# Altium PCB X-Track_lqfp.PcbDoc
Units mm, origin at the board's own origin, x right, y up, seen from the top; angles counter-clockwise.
Board outline 32.26 x 36.83 mm, 2 copper layers (Top Layer, Bottom Layer); 71 components, 50 nets, 272 pads, 61 vias.
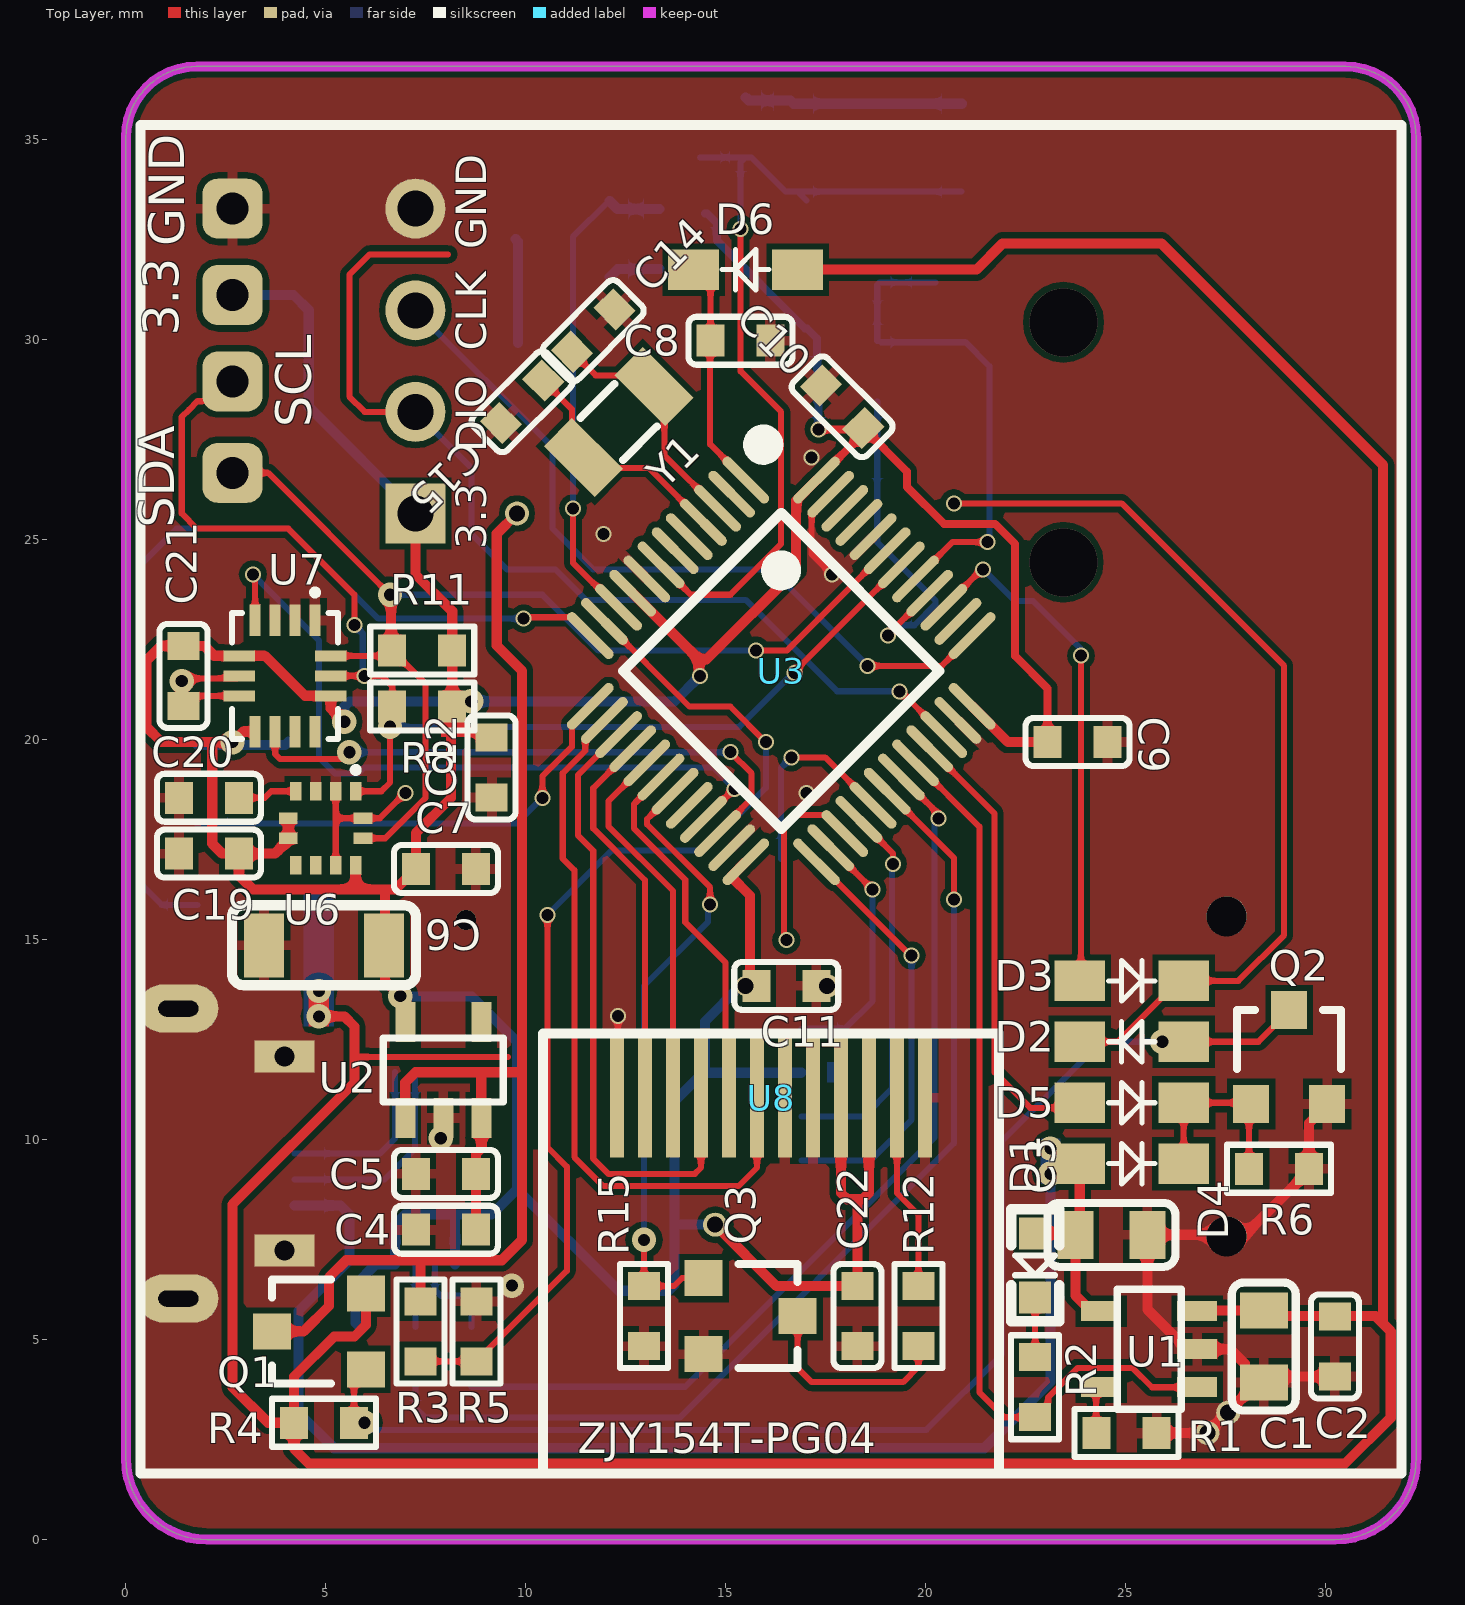
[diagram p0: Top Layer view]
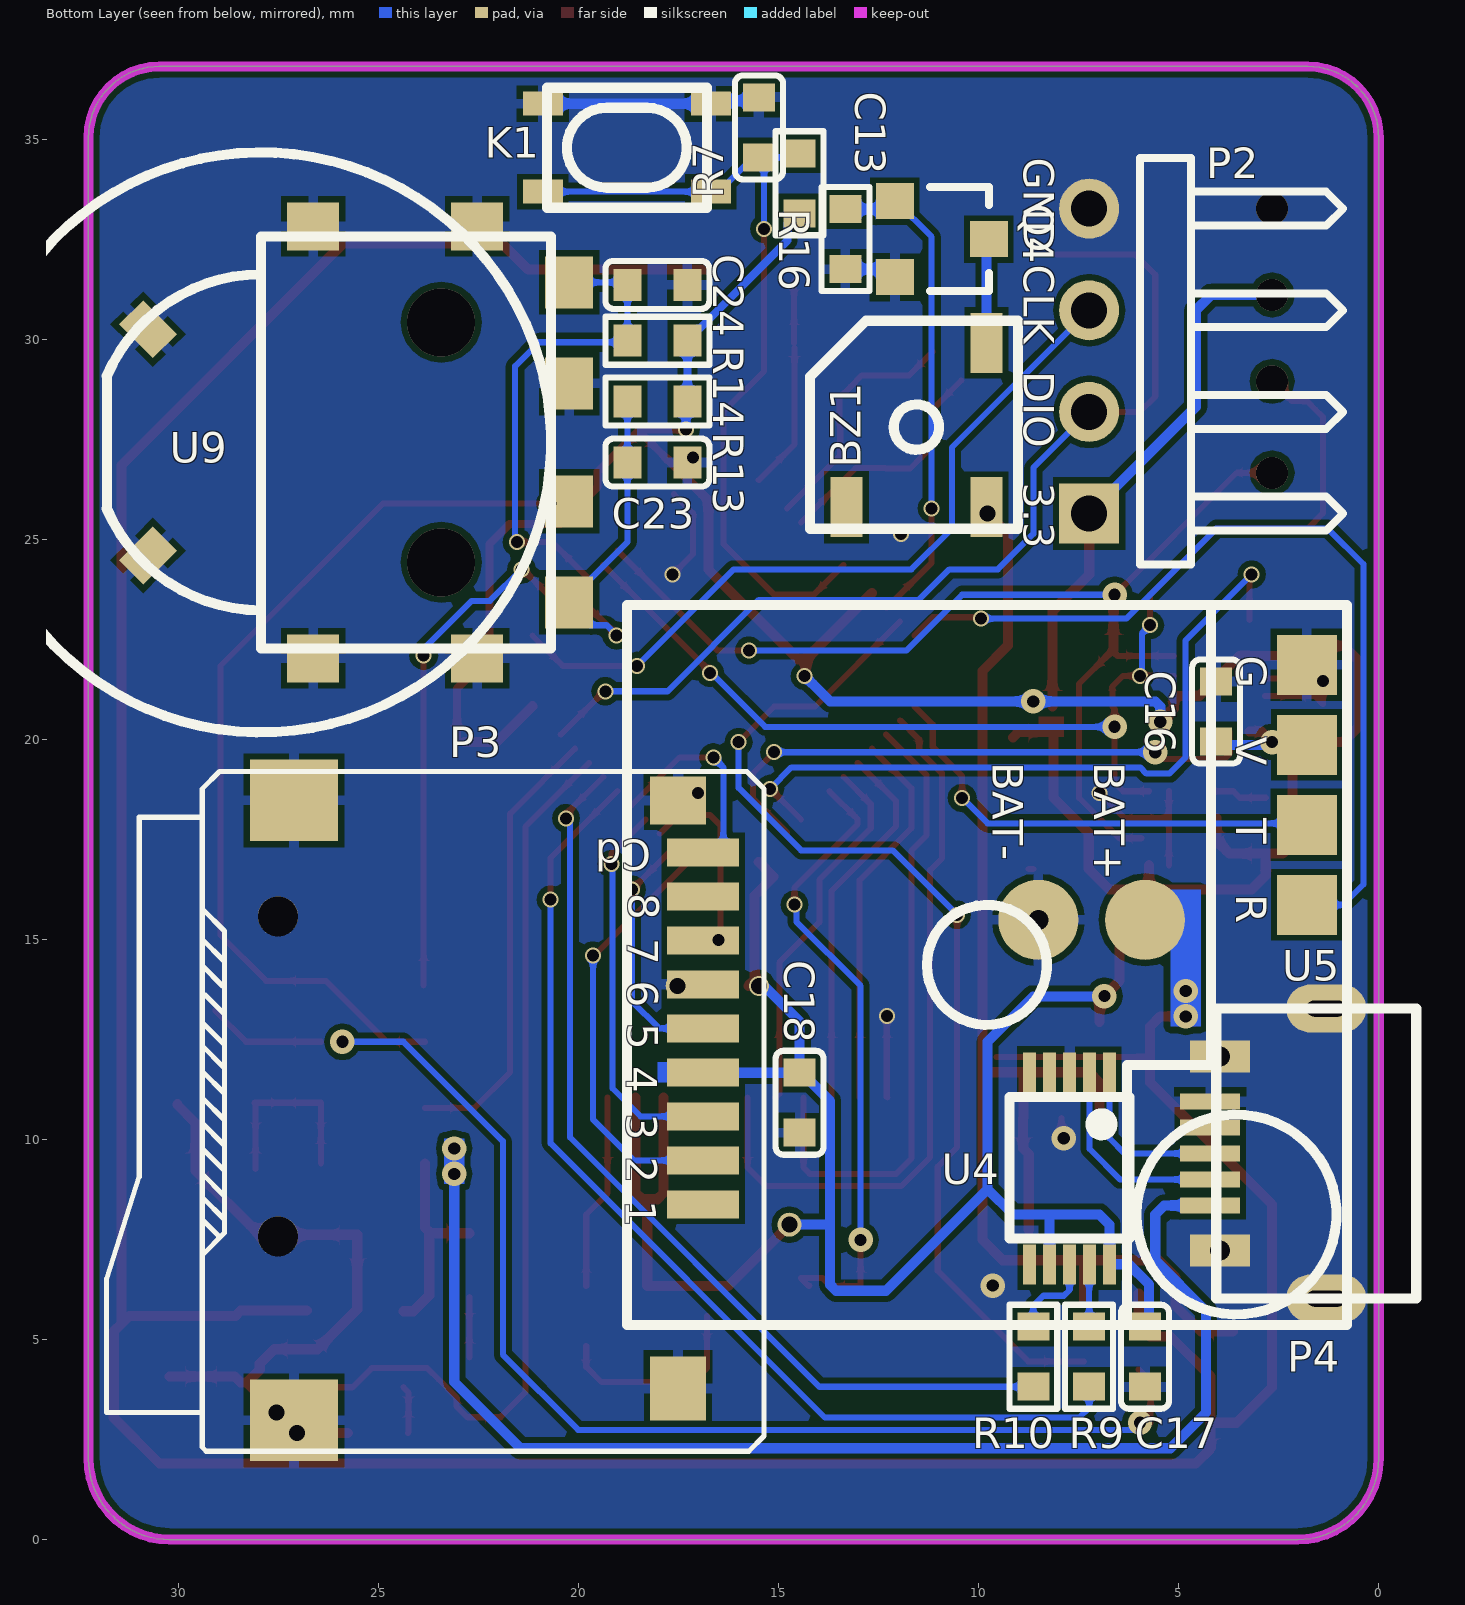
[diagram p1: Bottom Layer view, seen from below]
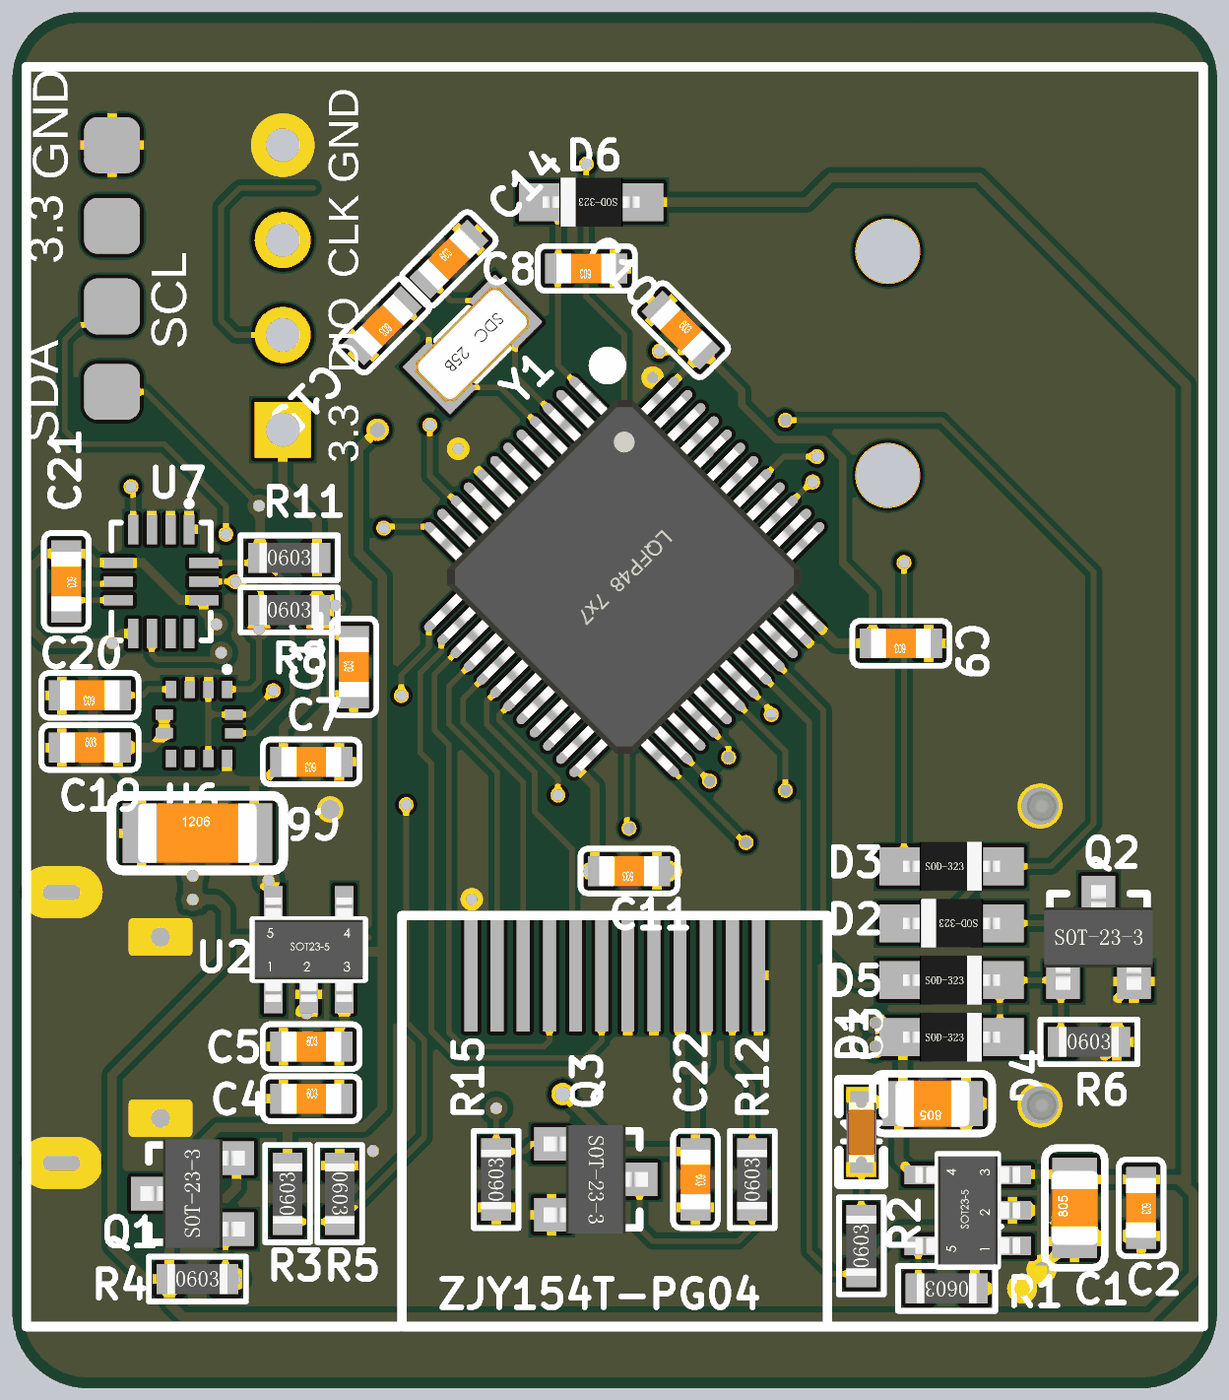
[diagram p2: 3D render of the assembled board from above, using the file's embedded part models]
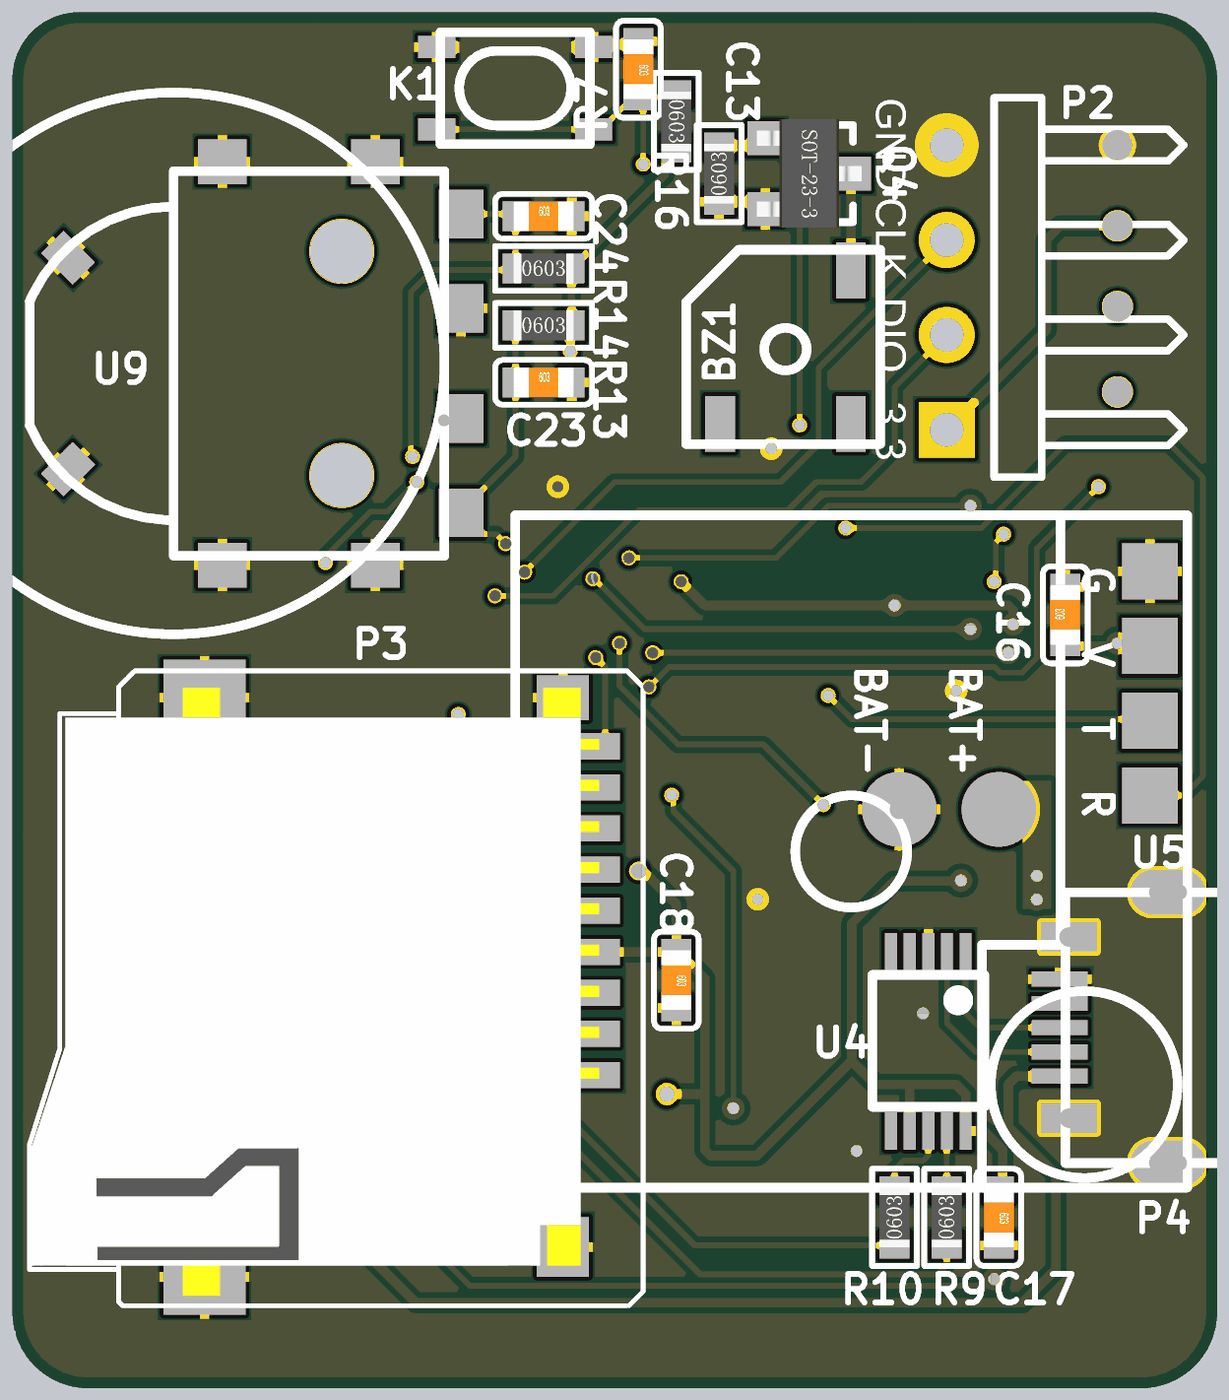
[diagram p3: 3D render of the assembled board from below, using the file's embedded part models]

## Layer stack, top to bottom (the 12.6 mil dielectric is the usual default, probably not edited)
Top Solder: solder mask 0.0102, Solder Resist, Dk 3.5
Top Layer: signal copper 0.0356
Dielectric 1: dielectric 0.32, FR-4, Dk 4.8
Bottom Layer: signal copper 0.0356
Bottom Solder: solder mask 0.0102, Solder Resist, Dk 3.5

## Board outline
0,2.032 0,35.052 cw(c1.778,35.052) 1.778,36.83 30.48,36.83 cw(c30.48,35.052) 32.258,35.052 32.258,2.032 cw(c30.226,2.032) 30.226,0 2.032,0 cw(c2.032,2.032)

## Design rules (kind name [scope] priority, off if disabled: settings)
Clearance [All] p1: gap=0.152 ignorepadtopadclearanceinfootprint=FALSE except(0: Arc-Hole Track-Hole SMDPad-Hole THPad-Hole Via-Hole Fill-Hole Poly-Hole Region-Hole Text-Hole)
ComponentClearance [All] p1 off: gap=0.254 collisioncheckmode=3 verticalgap=0.254 showdistances=FALSE
HoleSize [All] p1 off: absolutevalues=TRUE maxlimit=2.54 minlimit=0.025 maxpercent=80.000 minpercent=20.000
HoleToHoleClearance [All] p1 off: gap=0.254 allowstackedmicrovias=TRUE
LayerPairs [All] p1 off: enforce=TRUE
MinimumSolderMaskSliver [All] p1 off: minsoldermaskwidth=0.254
NetAntennae [All] p1 off: netantennaetolerance=0
PlaneConnect [All] p1: pad.planeconnectstyle=Relief pad.reliefexpansion=0.508 pad.reliefentries=4 pad.reliefconductorwidth=0.254 pad.reliefairgap=0.152 via.planeconnectstyle=Direct via.reliefexpansion=0.508 via.reliefentries=4 via.reliefconductorwidth=0.254 via.reliefairgap=0.152
PolygonConnect [All] p1: thpad.connectstyle=Direct thpad.reliefconductorwidth=0.254 thpad.reliefentries=4 thpad.polygonreliefangle="90 Angle" thpad.airgapwidth=0.152 smdpad.connectstyle=Relief smdpad.reliefconductorwidth=0.254 smdpad.reliefentries=4 smdpad.polygonreliefangle="90 Angle" smdpad.airgapwidth=0.152 via.connectstyle=Direct via.reliefconductorwidth=0.254 via.reliefentries=4 via.polygonreliefangle="90 Angle" via.airgapwidth=0.152
RoutingVias [All] p1: holewidth=0.305 width=0.61 viastyle="Through Hole" minholewidth=0.305 minwidth=0.61 maxholewidth=0.305 maxwidth=0.61
SilkToSilkClearance [All] p1 off: silktosilkclearance=0.254
SilkToSolderMaskClearance [IsPad] p1 off: minsilkscreentomaskgap=0.254 clearancetoexposedcopper=TRUE
SolderMaskExpansion [All] p1: expansion=0.102 istentingtop=FALSE
Width [All] p1: maxlimit=2.54 minlimit=0.152 preferedwidth=0.152
21 further rules are at their usual default settings.

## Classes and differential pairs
component class X-Track_Power: BAT+ BAT- C1 C2 C3 C4 C5 C6 C7 D1 D2 D3 D4 D5 Q1 Q2 R1 R2 R3 R4 R5 R6 U1 U2
component class X-Track_Sheet: 3.3 BZ1 C8 C9 C10 C11 C12 C13 C14 C15 C16 C17 C18 C19 C20 C21 C22 C23 C24 D6 GND K1 P2 P3 P4 Q3 Q4 R7 R8 R9 R10 R11 R12 R13 R14 R15 R16 SCL SDA U3 U4 U5 U6 U7 U8 U9 Y1

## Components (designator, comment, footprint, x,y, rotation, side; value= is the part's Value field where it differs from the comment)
3.3 "PAD1" PAD1-SMD-C 2.667,31.115 r0 top
BAT+ "BAT_IN" Pad_B 5.842,15.494 r90 bottom
BAT- "GND" Pad_B 8.509,15.494 r90 bottom
BZ1 "Buzzer" 蜂鸣器_SMD5020 11.557,27.813 r90 bottom
C1 "4.7UF" 电容_C0805 28.448,4.826 r90 top
C2 "104" 电容_C0603 30.226,4.826 r270 top
C3 "4.7UF" 电容_C0805 24.638,7.62 r180 top
C4 "104" 电容_C0603 8.001,7.747 r0 top
C5 "106" 电容_C0603 8.001,9.144 r0 top
C6 "22uF" 电容_C1206 4.953,14.859 r0 top
C7 "104" 电容_C0603 8.001,16.764 r180 top
C8 "104" 电容_C0603 15.367,29.972 r180 top
C9 "105" 电容_C0603 23.793,19.939 r180 top
C10 "105" 电容_C0603 17.907,28.321 r315 top
C11 "105" 电容_C0603 16.51,13.843 r180 top
C12 "105" 电容_C0603 9.144,19.304 r90 top
C13 "104" 电容_C0603 15.494,35.306 r270 bottom
C14 "22pf" 电容_C0603 11.684,30.226 r45 top
C15 "22pf" 电容_C0603 9.906,28.448 r225 top
C16 "105" 电容_C0603 4.064,20.701 r90 bottom
C17 "105" 电容_C0603 5.842,4.572 r270 bottom
C18 "104" 电容_C0603 14.478,10.922 r270 bottom
C19 "104" 电容_C0603 2.076,17.149 r0 top
C20 "104" 电容_C0603 2.076,18.546 r180 top
C21 "104" 电容_C0603 1.441,21.594 r270 top
C22 "104" 电容_C0603 18.288,5.588 r270 top
C23 "104" 电容_C0603 18.034,26.924 r180 bottom
C24 "104" 电容_C0603 18.034,31.369 r180 bottom
D1 "red" LED_0603 22.733,6.858 r270 top
D2 "1N4148" 二极管_SOD-323 25.146,12.446 r180 top
D3 "1N4148" 二极管_SOD-323 25.146,13.97 r0 top
D4 "1N4148" 二极管_SOD-323 25.146,9.398 r0 top
D5 "1N4148" 二极管_SOD-323 25.146,10.922 r0 top
D6 "1N4007" 二极管_SOD-323 15.494,31.75 r180 top
GND "PAD1" PAD1-SMD-C 2.667,33.274 r0 top
K1 "SKRP" 开关按键_SKRP 18.796,34.798 r0 bottom
P2 "Header 4" HDR1X4H 7.239,25.654 r90 bottom
P3 "Micro_SD" 接插件_Micro_SD 16.891,8.382 r270 bottom locked
P4 "MICRO USB" "接插件_MICRO 牛角插座 USB 直边" 4.064,9.652 r270 bottom
Q1 "AO3401" MOS_SOT-23 4.826,5.207 r90 top
Q2 "AON3400" MOS_SOT-23 29.083,12.065 r0 top
Q3 "AO3400" MOS_SOT-23 15.621,5.588 r270 top
Q4 "AO3400" MOS_SOT-23 10.922,32.512 r270 bottom
R1 "2K" 电阻_R0603 25.019,2.667 r180 top
R2 "1K" 电阻_R0603 22.733,3.81 r90 top
R3 "20K" 电阻_R0603 7.366,5.207 r90 top
R4 "20K" 电阻_R0603 4.953,2.921 r0 top
R5 "20K" 电阻_R0603 8.763,5.207 r270 top
R6 "20K" 电阻_R0603 28.829,9.271 r0 top
R7 "10K" 电阻_R0603 14.478,33.909 r270 bottom
R8 "10K" 电阻_R0603 7.41,20.832 r0 top
R9 "100R" 电阻_R0603 7.239,4.572 r90 bottom
R10 "100R" 电阻_R0603 8.636,4.572 r90 bottom
R11 "10K" 电阻_R0603 7.41,22.229 r0 top
R12 "10R" 电阻_R0603 19.812,5.588 r90 top
R13 "10K" 电阻_R0603 18.034,28.448 r180 bottom
R14 "10K" 电阻_R0603 18.034,29.972 r180 bottom
R15 "10K" 电阻_R0603 12.954,5.588 r90 top
R16 "10K" 电阻_R0603 13.335,32.512 r90 bottom
SCL "PAD1" PAD1-SMD-C 2.667,28.956 r0 top
SDA "PAD1" PAD1-SMD-C 2.667,26.67 r0 top
U1 "MCP73831" SOT23-5 26.784,3.81 r90 top
U2 "LP5907-3.3" SOT23-5 6.985,10.541 r0 top
U3 "AT32F403ACGU7" "LQFP48 7X7_L" 16.383,21.717 r225 top
U4 "CH340E" 串口_MSOP10 6.731,11.684 r0 bottom
U5 "HT1818Z3G5L" GPS-HTZN 18.796,23.368 r270 bottom
U6 "LIS3MDL" LGA-12_L2.0-W2.0-P0.50-BL 4.997,17.784 r180 top
U7 "LSM6DSM" LGA-14_L3.0-W2.5-P0.50-BL 3.981,21.594 r180 top
U8 "IPS154-12" "ZJY154T-PG04 FPC 0.7MM" 16.129,11.049 r270 top locked
U9 "Rotary Encoder" SIQ-02FVS3 27.94,27.432 r90 bottom locked
Y1 "32.768K" 晶振_3215 12.319,27.94 r225 top

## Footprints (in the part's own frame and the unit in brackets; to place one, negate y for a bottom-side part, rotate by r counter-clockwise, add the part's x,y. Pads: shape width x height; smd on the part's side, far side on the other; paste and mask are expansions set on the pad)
GPS-HTZN [mm]
  rect 1.5x1.5 smd: 1(1.5,17) 2(3.5,17) 3(5.5,17) 4(7.5,17)
  silkscreen extent 0,0 18,18
HDR1X4H [mm] "Connector; Header; 4 Position; Right Angle"
  rect 1.5x1.5 hole 0.9: 1(0,0)
  round 1.5 hole 0.9: 2(2.54,0) 3(5.08,0) 4(7.62,0)
  silkscreen extent -1.27,-6.35 8.89,-1.27
LED_0603 [mm]
  rect 0.8x0.8 smd paste-0.1: A(-0.8,0) K(0.8,0)
  silkscreen extent -1.4,-0.6 1.4,0.6, body extent -0.8,-0.4 0.82,0.4, height 0.6
LGA-12_L2.0-W2.0-P0.50-BL [mm]
  rect 0.28x0.465 smd: 1(-0.75,-0.925) 2(-0.25,-0.925) 3(0.25,-0.925) 4(0.75,-0.925) 7(0.75,0.925) 8(0.25,0.925) 9(-0.25,0.925) 10(-0.75,0.925)
  rect 0.465x0.28 smd: 5(0.933,-0.25) 6(0.933,0.25) 11(-0.933,0.25) 12(-0.933,-0.25)
  silkscreen extent -0.82,-1.53 -0.68,-1.38
LGA-14_L3.0-W2.5-P0.50-BL [mm]
  rect 0.28x0.785 smd: 1(-0.75,-1.393) 2(-0.25,-1.393) 3(0.25,-1.393) 4(0.75,-1.393) 8(0.75,1.393) 9(0.25,1.393) 10(-0.25,1.393) 11(-0.75,1.393)
  rect 0.785x0.28 smd: 5(1.142,-0.5) 6(1.142,0) 7(1.142,0.5) 12(-1.142,0.5) 13(-1.142,0) 14(-1.142,-0.5)
  silkscreen extent -1.33,-2.16 1.33,1.58
"LQFP48 7X7_L" [mm] "48脚，体宽7x7mm，脚距0.5mm"
  oval 0.25x1.55 smd: 1(-2.75,-4) 2(-2.25,-4) 3(-1.75,-4) 4(-1.25,-4) 5(-0.75,-4) 6(-0.25,-4) 7(0.25,-4) 8(0.75,-4) 9(1.25,-4) 10(1.75,-4) 11(2.25,-4) 12(2.75,-4) 25(2.75,4) 26(2.25,4) 27(1.75,4) 28(1.25,4) 29(0.75,4) 30(0.25,4) 31(-0.25,4) 32(-0.75,4) 33(-1.25,4) 34(-1.75,4) 35(-2.25,4) 36(-2.75,4)
  oval 1.55x0.25 smd: 13(4,-2.75) 14(4,-2.25) 15(4,-1.75) 16(4,-1.25) 17(4,-0.75) 18(4,-0.25) 19(4,0.25) 20(4,0.75) 21(4,1.25) 22(4,1.75) 23(4,2.25) 24(4,2.75) 37(-4,2.75) 38(-4,2.25) 39(-4,1.75) 40(-4,1.25) 41(-4,0.75) 42(-4,0.25) 43(-4,-0.25) 44(-4,-0.75) 45(-4,-1.25) 46(-4,-1.75) 47(-4,-2.25) 48(-4,-2.75)
  silkscreen extent -3.93,-4.57 2.79,2.79, body extent -4.5,-4.5 4.5,4.5, height 1.45
MOS_SOT-23 [mm]
  rect 0.9x0.95 smd: 1(-0.95,-1.175) 2(0,1.175) 3(0.95,-1.175)
  silkscreen extent -1.3,-0.3 1.3,1.18, body extent -1.45,-1.4 1.45,1.4, height 1.2
PAD1-SMD-C [mm] "引线焊盘"
  rrect50% 1.5x1.5 smd: 1(0,0)
Pad_B [mm]
  round 2 smd: 1(0,0)
SIQ-02FVS3 [mm]
  rect 1.3x1.2 smd: 1(-4,-7.7) 2(-1.475,-7.7) 3(1.475,-7.7) 4(4,-7.7)
  rect 1.2x1.3 smd: 5(-5.4,-5.4) 5(-5.4,-1.3) 5(5.4,-5.4) 5(5.4,-1.3)
  rect 0.85x1.2 smd rot 45: 5(-2.828,2.828)
  rect 0.85x1.2 smd rot 135: 5(2.828,2.828)
  silkscreen extent -7.25,-7.25 7.25,7.25
SOT23-5 [mm]
  rect 0.5x1 smd: 1(0,0) 2(0.95,0) 3(1.9,0) 4(1.9,2.4) 5(0,2.4)
  silkscreen extent -0.55,0.4 2.45,2, body extent -0.5,-0.2 2.4,2.6, height 1.09
"ZJY154T-PG04 FPC 0.7MM" [mm]
  rect 3x0.35 smd: 1(0,3.85) 2(0,3.15) 3(0,2.45) 4(0,1.75) 5(0,1.05) 6(0,0.35) 7(0,-0.35) 8(0,-1.05) 9(0,-1.75) 10(0,-2.45) 11(0,-3.15) 12(0,-3.85)
  silkscreen extent -24.32,-15.76 9.4,15.76
串口_MSOP10 [mm]
  rect 0.32x1 smd: 1(0,0) 2(0.5,0) 3(1,0) 4(1.5,0) 5(2,0) 6(2,4.8) 7(1.5,4.8) 8(1,4.8) 9(0.5,4.8) 10(0,4.8)
  silkscreen extent -0.5,0.62 2.5,4.15
二极管_SOD-323 [mm]
  rect 1.27x1.016 smd: A(-1.3,0) K(1.3,0)
  silkscreen extent -0.58,-0.51 0.58,0.51, body extent -1.3,-0.65 1.3,0.65, height 1
开关按键_SKRP [mm]
  rect 1x0.6 smd: 1(-2.1,-1.1) 1(2.1,-1.1) 2(-2.1,1.1) 2(2.1,1.1)
  silkscreen extent -2,-1.5 2,1.5
"接插件_MICRO 牛角插座 USB 直边" [mm]
  oval 1.2x2 hole 0.4 slot 1 at 90 deg: 0(-3.625,2.75) 0(3.625,2.75)
  rect 0.8x1.5 hole 0.5: 0(-2.425,0.1) 0(2.425,0.1)
  rect 0.4x1.5 smd: 1(1.3,-0.15) 2(0.65,-0.15) 3(0,-0.15) 4(-0.65,-0.15) 5(-1.3,-0.15)
  silkscreen extent -3.62,0 3.62,5
接插件_Micro_SD [mm]
  rect 2.032x2.2 smd: 0(-10.1,-10.227) 0(5.4,-10.227)
  rect 1.2x1.4 smd: 0(-10.1,-0.627)
  round 1 hole 1 unplated: 0(-7.2,-10.627) 0(0.8,-10.627)
  rect 1.6x1.4 smd: 0(4.6,-0.627)
  rect 0.7x1.8 smd: 1(0,0) 2(-1.1,0) 3(-2.2,0) 4(-3.3,0) 5(-4.4,0) 6(-5.5,0) 7(-6.6,0) 8(-7.7,0) 9(-8.8,0)
  silkscreen extent -10.82,-14.91 6.17,1.52, body extent -10.37,-14.85 5.9,0.34, height 1.8
晶振_3215 [mm] "XTAL SMD 3.2 x 1.5 mm"
  rect 1x1.8 smd: 1(-1.25,0) 2(1.25,0)
  silkscreen extent -0.6,-0.75 0.6,0.75, body extent -1.6,-0.75 1.6,0.75, height 0.81
电容_C0603 [mm]
  rect 0.7x0.8 smd: 1(-0.75,0) 2(0.75,0)
  silkscreen extent -1.3,-0.6 1.3,0.6, body extent -0.8,-0.4 0.8,0.4, height 0.3
电容_C0805 [mm]
  rect 0.9x1.2 smd: 1(-0.9,0) 2(0.9,0)
  silkscreen extent -1.6,-0.8 1.6,0.8, body extent -1,-0.62 1,0.63, height 0.77
电容_C1206 [mm]
  rect 1x1.6 smd: 1(-1.5,0) 2(1.5,0)
  silkscreen extent -2.3,-1 2.3,1, body extent -1.6,-0.8 1.6,0.8, height 1
电阻_R0603 [mm]
  rect 0.7x0.8 smd: 1(-0.75,0) 2(0.75,0)
  silkscreen extent -1.3,-0.6 1.3,0.6, body extent -0.8,-0.4 0.8,0.4, height 0.45
蜂鸣器_SMD5020 [mm]
  rect 1.5x0.8 smd: 0(-2,1.75) 1(-2,-1.75) 2(2.108,-1.753)
  silkscreen extent -2.54,-2.54 2.66,2.66

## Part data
3.3 GND SCL SDA: "引线焊盘"
BAT+ BAT-: library part Pad
BZ1: library part BZ
C1 C2 C3 C4 C5 C6 C7 C8 C9 C10 C11 C12 C13 C14 C15 C16 C17 C18 C19 C20 C21 C22 C23 C24: library part cap
D1: library part LED
D2 D3 D4 D5 D6: library part Diode, _Current=1A, _Voltage=40V
K1: library part SW-PB
P2: "Header, 4-Pin"
P3: _Value=TF,9PIN
P4: library part "MICRO USB 5PIN", _Value=5PIN
Q1: library part MOSFET-P, _Current=40A, _Voltage=20V
Q2 Q3 Q4: library part MOSFET-N, _Current=150A, _Voltage=30V
R1 R2 R3 R4 R5 R6 R7 R9 R10 R15 R16: library part Res
R8 R11 R12 R13 R14: library part Res, _Power=1/8W
U1: "线性充电管理控制器"
U2: library part LP5907, "LDO"
U3: library part AT32F403CGU6
U6: library part LIS3DMDL
Y1: library part XTAL_A

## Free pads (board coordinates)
  round 0.6 hole 0.4: 2(9.779,25.654) 3(27.039,2.667) 4(27.559,3.175) 5(14.732,7.874) 6(17.526,13.843)

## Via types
v1: diameter 0.4, hole 0.3, Top Layer to Bottom Layer, 36 vias
v2: diameter 0.61, hole 0.305, Top Layer to Bottom Layer, tented both sides, 17 vias
v3: diameter 0.8, hole 0.8, Top Layer to Bottom Layer, 4 vias
v4: diameter 1.7, hole 1.7, Top Layer to Bottom Layer, 2 vias
v5: diameter 0.5, hole 0.5, Top Layer to Bottom Layer, 1 vias
v6: diameter 0.5, hole 0.4, Top Layer to Bottom Layer, 1 vias

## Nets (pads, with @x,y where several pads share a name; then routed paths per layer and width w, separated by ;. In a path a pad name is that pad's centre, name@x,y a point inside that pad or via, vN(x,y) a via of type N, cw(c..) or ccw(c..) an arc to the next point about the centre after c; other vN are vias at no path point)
3V3: 3.3.1 C6.2 C7.2 C9.2 C10.2 C11.2 C12.2 C16.1 C17.1 C18.1 C19.2 C21.1 C22.1 P2.1 P3.4 pad.5 R7.2 R8.2 R11.2 R13.2 R14.2 U2.5 U3.9 U3.24 U3.36 U3.48 U4.7 U4.10 U5.2 U6.5 U6.6 U6.10 U7.5 U7.8 U7.12 U8.3 U8.4 | length 134.9
  Top Layer w0.2: U3.48 C10.2@18.437,27.66 ; v1(17.32,27.755) 18.402,27.755 C10.2 19.531,26.697 19.531,26.316 20.458,25.389 21.733,25.389 22.233,24.889 22.233,22.09 23.043,21.28 C9.2
  Top Layer w0.254: U7.8 2.929,20.201 v2(2.667,19.939) 2.159,19.939 ; U6.5 4.064,17.486 3.727,17.149 C19.2 ; v2(5.461,20.447) 5.123,20.785 U7.12 4.481,21.094 3.481,22.094 U7.5 2.211,22.094 1.961,22.344 C21.1 0.881,22.344 0.508,21.971 0.508,20.32 0.889,19.939 2.159,19.939 ; U6.10 5.747,16.256 ; U2.5 6.985,13.462 6.477,13.97 6.477,16.256 ; P2.1 7.239,24.13 8.16,23.209 R11.2 R8.2 ; C12.2 9.005,20.193 8.128,20.193 8.128,18.542 7.251,17.665 C7.2 6.743,16.256 6.477,16.256 ; U3.9 14.323,22.009 ; v1(14.351,21.59) 14.323,21.618 14.323,22.009 ; pad.5 16.268,6.338 C22.1 18.288,8.509 ; U3.24 15.131,16.576 15.131,16.573 15.602,16.102 15.602,14.001 C11.2 ; U3.48 16.756,25.979 16.756,24.249 14.516,22.009 14.323,22.009 ; U8.4 17.879,8.664 18.034,8.509 18.415,8.509 18.579,8.673 U8.3 ; U3.36 22.05,19.939 C9.2@22.872,19.939 ; 2.159,19.939 2.159,17.399 2.409,17.149 C19.2 ; C19.2 2.826,16.605 3.175,16.256 5.747,16.256 ; 5.747,16.256 6.477,16.256
  Bottom Layer w0.2: R7.2 14.528,33.159 14.778,32.909 14.778,32.478 16.984,30.272 17.034,30.272 17.284,30.022 R14.2 R13.2 17.32,28.412 v1(17.32,27.755)
  Bottom Layer w0.254: U5.2 C16.1@3.981,19.868 ; v2@2.667,19.868 C16.1@3.981,19.868 ; v3(2.667,31.115) 4.191,31.115 4.572,30.734 4.572,28.321 P2.1 ; C16.1 C16.1@3.981,19.868 ; v2(5.461,20.447) 5.461,20.828 5.588,20.955 v2(8.636,20.955) 13.716,20.955 v1(14.351,21.59) ; C17.1 5.741,5.423 5.741,6.376 6.249,6.884 U4.10 6.731,7.874 6.985,8.128 8.231,8.128 ; v2(6.858,13.589) 6.867,13.58 8.645,13.58 9.779,12.446 9.779,8.763 ; U4.7 8.231,8.128 ; pad.5 13.716,7.874 ; v6@15.621,13.843 15.367,13.843 14.478,12.954 C18.1 ; P3.4 16.881,11.672 C18.1 ; 8.231,8.128 9.144,8.128 9.779,8.763 ; 9.779,8.763 12.319,6.223 13.567,6.223 13.716,6.372 13.716,7.874 ; 13.716,7.874 13.716,10.96 14.428,11.672 C18.1
  other v6: 15.494,13.843
BAT: BZ1.1 C4.2 C5.2 pad.2 Q1.2 R3.2 U2.1 U2.3 | length 35.2
  Top Layer w0.254: Q1.2 4.445,5.207 5.08,5.842 5.08,6.556 5.509,6.985 7.366,6.985 ; U2.1 6.985,11.43 7.239,11.684 9.906,11.684 ; R3.2 7.366,6.985 ; C4.2 C5.2 8.751,9.64 8.89,9.779 8.89,10.536 U2.3 8.885,11.679 ; pad.2 9.271,25.146 9.271,22.352 9.906,21.717 9.906,11.684 ; 7.366,6.985 9.398,6.985 9.906,7.493 9.906,11.684
BAT_CHG_DET: R2.1 U1.1 U3.32 | length 22.9
  Top Layer w0.152: U3.32 21.336,17.825 21.336,3.683 21.959,3.06 R2.1 22.783,3.06 23.057,3.334 23.057,3.556 23.505,4.005 23.789,4.289 25.175,4.289 25.654,3.81 U1.1
BAT_DET: R3.1 R5.2 U3.11 | length 26.9
  Top Layer w0.152: R3.1 R5.2 11.024,6.718 11.024,9.323 10.541,9.806 v1(10.541,15.621) ; U3.11 14.09,20.828 15.113,20.828 v1(16.002,19.939)
  Bottom Layer w0.152: v1(10.541,15.621) 12.152,17.232 14.438,17.232 16.002,18.796 v1(16.002,19.939)
BAT_IN: BAT+.1 C1.2 C2.1 D6.A Q1.3 R4.1 U1.3 | length 95.9
  Top Layer w0.152: 5.715,12.065 9.55,12.065
  Top Layer w0.254: v2(4.826,13.081) 5.461,13.081 5.715,12.827 5.715,12.065 5.715,11.43 2.667,8.382 2.667,3.81 3.556,2.921 R4.1 ; Q1.3 6.001,5.366 5.715,5.08 5.207,5.08 4.203,4.076 R4.1 ; D6.A 21.266,31.75 21.923,32.407 25.886,32.407 31.432,26.86 31.432,5.397 ; U1.3@26.797,5.726 C1.2 28.586,5.588 30.226,5.588 31.242,5.588 31.432,5.397 ; R4.1 4.203,2.274 4.572,1.905 30.48,1.905 31.623,3.048 31.623,5.207 31.432,5.397
  other v2: 4.826,13.716
BUZZ: Q4.1 R16.2 U3.10 | length 12.4
  Top Layer w0.152: v1(11.176,25.781) 11.176,24.423 12.291,23.308 U3.10
  Bottom Layer w0.152: v1(11.176,25.781) 11.176,32.566 12.072,33.462 Q4.1
  Bottom Layer w0.254: Q4.1 12.297,33.262 R16.2
EC_A: C23.1 R13.1 U3.40 U9.1 | length 8.7
  Top Layer w0.152: v1(19.05,22.606) 19.05,22.616 U3.40
  Bottom Layer w0.152: R13.1 C23.1 18.784,24.938 20.24,23.482 U9.1 20.24,23.382 19.716,22.858 19.302,22.858 v1(19.05,22.606)
EC_B: C24.1 R14.1 U3.41 U9.4 | length 12.4
  Top Layer w0.152: U3.41 20.663,24.937 v1(21.545,24.937)
  Bottom Layer w0.152: R14.1 C24.1 18.847,31.432 U9.4 ; R14.1@18.885,29.934 20.993,29.934 21.59,29.337 21.59,24.981 v1(21.545,24.937)
EC_KEY: D2.K D3.K U9.2 | length 22.9
  Top Layer w0.152: v1(20.701,25.908) 24.892,25.908 28.956,21.844 28.956,15.113 27.813,13.97 D3.K 26.319,13.97 24.795,12.446 D2.K
EC_KEY_DET: D3.A U3.39 | length 13.1
  Top Layer w0.152: U3.39 21.398,24.257 v1(21.43,24.257) v1@21.463,24.257 ; D3.A@23.876,13.852 v1(23.876,22.098)
  Bottom Layer w0.152: v1(21.43,24.257) 22.219,23.468 22.677,23.468 23.876,22.269 v1(23.876,22.098)
GND: BAT-.1 C1.1 C2.2 C3.1 C4.1 C5.1 C6.1 C7.1 C8.1 C9.1 C10.1 C11.1 C12.1 C13.1 C14.2 C15.2 C16.2 C17.2 C18.2 C19.1 C20.2 C21.2 C22.2 C23.2 C24.2 GND.1 K1.1 P2.4 P3.0 P3.6 P4.0 P4.5 pad.3 pad.4 pad.6 Q2.3 Q3.3 Q4.3 R1.1 R5.1 R6.2 R15.1 R16.1 U1.2 U2.2 U3.8 U3.23 U3.35 U3.44 U3.47 U4.3 U5.1 U6.2 U6.3 U6.9 U6.12 U7.1 U7.2 U7.3 U7.6 U7.7 U8.1 U8.5 U8.6 U8.12 U9.3 U9.5 | length 36.4
  Top Layer w0.152: U7.7 1.603,21.094 1.397,20.887 v2(1.397,21.463) 1.464,21.53 2.774,21.53 U7.6 ; U6.9 5.247,18.034 ; U6.2 5.247,18.034 ; v1(6.985,18.669) 6.35,18.034 U6.12 5.247,18.034 ; v2(7.874,10.033) 7.935,10.094 U2.2 ; C7.1@8.636,16.764 C7.1 ; U8.12 12.299,11.069 v1(12.299,13.086) ; U3.47 17.145,25.661 17.145,24.638 v1(17.653,24.13)
  Top Layer w0.254: R1.1 pad.3 C1.1@28.298,3.926 ; Q2.3 30.033,10.865 29.579,10.411 R6.2 29.579,9.221 27.978,7.62 C3.1 25.538,5.756 26.534,4.76 U1.2 27.614,4.76 27.975,4.399 27.975,4.249 C1.1@28.298,3.926 ; C2.2 28.598,4.076 C1.1 C1.1@28.298,3.926
  Bottom Layer w0.254: Q4.3 12.297,31.762 R16.1 ; C13.1 15.573,35.977 16.617,35.977 16.696,35.898 K1.1@20.896,35.898
  other v1: 17.018,18.669 11.938,25.146 17.145,27.051
  other v2: 9.652,6.35
  other v3: 2.667,33.274
  other v5: 8.509,15.494
GPS_RX: U3.12 U5.4 | length 22.4
  Top Layer w0.152: v1(9.943,23.024) 9.979,23.06 11.151,23.06 U3.12
  Bottom Layer w0.152: U5.4 0.896,15.868 0.381,16.383 0.381,24.384 1.27,25.273 4.064,25.273 6.313,23.024 v1(9.943,23.024)
GPS_TX: U3.13 U5.3 | length 11.7
  Top Layer w0.152: v1(10.414,18.542) 10.414,19.085 11.151,19.822 11.151,20.374 U3.13
  Bottom Layer w0.152: U5.3 1.835,17.907 9.779,17.907 v1(10.414,18.542)
IMU_INT1: U3.21 U7.4 | length 18.4
  Top Layer w0.152: v1(3.175,24.13) 3.23,24.075 U7.4 ; U3.21 14.444,18.005 15.21,18.771 v1(15.215,18.771)
  Bottom Layer w0.152: v1(3.175,24.13) 4.826,22.479 4.826,19.558 5.232,19.152 5.809,19.152 5.961,19.304 14.682,19.304 v1(15.215,18.771)
IMU_INT2: U3.22 U7.9 | length 14.7
  Top Layer w0.152: U7.9 3.73,19.638 3.857,19.511 5.414,19.511 v2(5.588,19.685) ; U3.22 14.792,17.678 15.644,18.529 15.644,19.154 v1(15.113,19.685)
  Bottom Layer w0.152: v2(5.588,19.685) v1(15.113,19.685)
MCU_RX: R10.1 U3.31 | length 23.6
  Top Layer w0.152: U3.31 20.273,18.181 20.273,18.081 v1(20.32,18.034)
  Bottom Layer w0.152: R10.1 13.982,3.822 20.218,10.058 20.218,17.932 v1(20.32,18.034)
MCU_SCL: R8.1 SCL.1 U3.42 U6.1 U7.13 | length 30.8
  Top Layer w0.152: v3(2.667,28.956) 2.178,28.467 1.911,28.467 1.904,28.46 1.79,28.46 1.581,28.251 1.397,28.067 1.397,25.654 1.778,25.273 4.064,25.273 5.715,23.622 v1(5.715,22.86) ; U7.13 6.394,21.594 6.66,21.328 R8.1 6.604,20.776 v2(6.604,20.32) 6.604,18.923 6.39,18.709 U6.1 ; v1(16.715,21.668) 16.715,21.695 U3.42
  Bottom Layer w0.152: v1(5.715,22.86) 5.922,22.653 5.922,21.637 v1(5.969,21.59) ; v2(6.604,20.32) 15.34,20.32 16.687,21.668 v1(16.715,21.668)
MCU_SDA: R11.1 SDA.1 U3.43 U6.11 U7.14 | length 28.3
  Top Layer w0.152: v3(2.667,26.67) 3.556,26.67 v2(6.604,23.622) ; U7.14 6.525,22.094 R11.1 7.493,21.395 7.493,18.542 6.485,17.534 U6.11 ; v1(15.748,22.225) 16.524,22.225 19.021,24.722 U3.43
  Top Layer w0.254: v2(6.604,23.622) 6.632,23.594 6.632,22.257 R11.1
  Bottom Layer w0.152: v2(6.604,23.622) 10.414,23.622 11.811,22.225 v1(15.748,22.225)
MCU_TX: R9.1 U3.30 | length 26.4
  Top Layer w0.152: U3.30 20.701,17.045 v1(20.701,16.002)
  Bottom Layer w0.152: R9.1 7.239,3.302 7.493,3.048 13.843,3.048 20.701,9.906 v1(20.701,16.002)
NetBZ1_2: BZ1.2 Q4.2 | length 2.6
  Bottom Layer w0.254: Q4.2 9.804,32.455 BZ1.2
NetC20_1: C20.1 U6.4 | length 1.5
  Top Layer w0.152: C20.1 3.473,18.546 3.636,18.709 U6.4
NetD1_K: D1.K R2.2 | length 1.5
  Top Layer w0.152: R2.2 D1.K
NetD2_A: D2.A Q1.1 Q2.2 R4.2 | length 31.6
  Top Layer w0.152: R4.2 5.703,3.959 Q1.1 ; D2.A 28.314,12.446 29.083,13.215 Q2.2
  Bottom Layer w0.152: v2(5.969,2.921) 6.147,2.743 20.015,2.743 21.897,4.625 21.897,9.959 24.384,12.446 v2(25.908,12.446)
NetD4_K: D4.K D5.K Q2.1 R6.1 | length 4.8
  Top Layer w0.152: D4.K D5.K 28.101,10.922 28.079,10.9 R6.1
NetP4_2: P4.2 U4.2 | length 5.2
  Bottom Layer w0.152: P4.2 6.462,9.002 7.231,9.771 U4.2
NetP4_3: P4.3 U4.1 | length 4.3
  Bottom Layer w0.152: P4.3 6.35,9.652 6.731,10.033 U4.1
NetQ3_2: Q3.2 R12.1 | length 5.1
  Top Layer w0.152: Q3.2 16.796,4.286 17.145,3.937 19.431,3.937 19.812,4.318 R12.1
NetR1_2: R1.2 U1.5 | length 1.2
  Top Layer w0.152: R1.2 24.257,2.679 24.257,3.683 U1.5
NetR9_2: R9.2 U4.9 | length 1.6
  Bottom Layer w0.152: U4.9 7.239,6.876 R9.2
NetR10_2: R10.2 U4.8 | length 2.2
  Bottom Layer w0.152: U4.8 7.731,6.239 7.874,6.096 8.382,6.096 8.636,5.842 R10.2
OSC32_IN: C14.1 U3.3 Y1.1 | length 6.1
  Top Layer w0.152: C14.1 11.743,29.107 12.92,29.107 Y1.1 13.486,28.541 13.486,27.942 13.462,27.918 13.462,27.113 U3.3
OSC32_OUT: C15.1 U3.4 Y1.2 | length 6
  Top Layer w0.152: C15.1 11.152,28.262 11.152,27.339 Y1.2 11.718,26.773 12.317,26.773 12.331,26.787 13.081,26.787 U3.4
PWR_EN: D5.A U3.33 | length 11.3
  Top Layer w0.152: U3.33 21.717,18.151 21.717,11.684 22.606,10.795 D5.A@23.846,10.795
RST: C13.2 K1.2 R7.1 U3.7 | length 21.2
  Top Layer w0.152: U3.7 14.124,23.622 15.113,23.622 16.383,24.892 16.383,28.194 15.367,29.21 v1(15.367,32.766)
  Bottom Layer w0.152: R7.1@14.351,34.556 C13.2 ; v1(15.367,32.766) 15.367,34.429 C13.2 ; K1.2@17.018,33.474 K1.2@16.794,33.698 ; K1.2@20.896,33.698 K1.2@16.794,33.698 ; C13.2 15.638,34.556 16.496,33.698 16.696,33.698 K1.2@16.794,33.698
SCR_BLK: Q3.1 R15.2 U3.19 | length 15.9
  Top Layer w0.152: R15.2 13.704,6.338 13.904,6.538 Q3.1 14.246,6.338 Q3.1@14.234,6.35 ; v2(12.954,7.493) 12.954,6.348 R15.2@12.965,6.337 ; U3.19 13.028,18.009 13.028,17.883 14.605,16.306 v1(14.605,15.875)
  Bottom Layer w0.152: v2(12.954,7.493) 12.954,13.843 14.558,15.447 14.558,15.828 v1(14.605,15.875)
SCR_CS: U3.18 U8.8 | length 9.3
  Top Layer w0.152: U3.18 12.7,18.388 12.7,17.78 13.984,16.496 13.984,15.435 14.986,14.433 14.986,11.142 U8.8
SCR_DC: U3.14 U8.7 | length 18.3
  Top Layer w0.152: U3.14 11.486,20.002 11.486,19.725 10.922,19.162 10.922,17.026 11.214,16.734 11.214,9.564 11.939,8.839 15.316,8.839 15.779,9.302 U8.7
SCR_LEDK: R12.2 U8.2 | length 4.9
  Top Layer w0.152: U8.2 19.279,8.661 19.812,8.128 R12.2
SCR_RES: U3.16 U8.11 | length 9.7
  Top Layer w0.152: U3.16 11.684,18.786 11.684,17.78 12.979,16.485 U8.11
SCR_SCL: U3.15 U8.9 | length 15.8
  Top Layer w0.152: U3.15 11.303,19.112 11.303,17.604 11.684,17.223 11.684,9.525 12.065,9.144 14.224,9.144 14.379,9.299 U8.9
SCR_SDA: U3.17 U8.10 | length 9.4
  Top Layer w0.152: U3.17 12.065,18.46 12.065,17.83 13.679,16.216 U8.10
SD_CD: P3.9 U3.29 | length 5.2
  Top Layer w0.152: v1(16.637,19.558) 17.481,19.558 U3.29
  Bottom Layer w0.152: P3.9@16.383,17.018 16.383,19.304 v1(16.637,19.558)
SD_CS: P3.2 U3.25 | length 10.6
  Top Layer w0.152: U3.25 19.606,14.605 v1(19.645,14.605)
  Bottom Layer w0.152: P3.2 18.626,9.482 19.642,10.498 19.642,14.602 v1(19.645,14.605)
SD_MISO: P3.7 U3.27 | length 4.7
  Top Layer w0.152: v1(16.51,14.986) 16.453,15.043 16.453,17.85 16.714,18.111 17.514,18.111 U3.27
SD_MOSI: P3.3 U3.28 | length 9.6
  Top Layer w0.152: U3.28 19.177,17.155 v1(19.177,16.891)
  Bottom Layer w0.152: P3.3 18.456,10.582 19.152,11.278 19.152,16.866 v1(19.177,16.891)
SD_SCK: P3.5 U3.26 | length 6.4
  Top Layer w0.152: U3.26 v1(18.669,16.249) v1@18.669,16.148
  Bottom Layer w0.152: P3.5 17.989,12.782 18.669,13.462 v1(18.669,16.249)
SWCLK: P2.3 U3.37 | length 19.1
  Top Layer w0.152: v1(18.542,21.844) 20.399,21.844 U3.37
  Bottom Layer w0.152: P2.3 10.668,27.305 10.668,25.273 11.684,24.257 16.129,24.257 v1(18.542,21.844)
SWDIO: P2.2 U3.34 | length 25.1
  Top Layer w0.152: P2.2 5.969,28.194 5.588,28.575 5.588,31.623 6.096,32.131 8.053,32.131 ; v1@19.304,21.209 v1(19.335,21.209) 19.366,21.209 U3.34
  Bottom Layer w0.152: P2.2 8.636,26.797 8.636,25.146 9.525,24.257 10.736,24.257 11.498,23.495 15.494,23.495 17.78,21.209 v1(19.335,21.209)
USB_VCC: C3.2 D1.A D4.A P4.1 U1.4 | length 36.9
  Top Layer w0.254: D1.A C3.2@23.7,7.658 ; D4.A 23.846,7.804 C3.2@23.7,7.658 ; U1.4 24.134,5.71 23.738,6.106 C3.2 C3.2@23.7,7.658
  Bottom Layer w0.254: P4.1 5.364,8.352 5.588,8.128 5.588,6.985 4.318,5.715 4.318,3.175 5.207,2.286 21.458,2.286 23.114,3.942 v2@23.114,8.852
  other v2: 23.114,9.144 23.114,9.779
VBAT: C8.2 D6.K U3.1 | length 5.3
  Top Layer w0.152: D6.K@14.575,31.496 14.617,31.454 C8.2 C8.2@14.617,29.922 ; C8.2@14.605,29.783 14.605,27.384 U3.1
pads on no net: BZ1.0 P3.1 P3.8 P4.4 U2.4 U3.2 U3.5 U3.6 U3.20 U3.38 U3.45 U3.46 U4.4 U4.5 U4.6 U6.7 U6.8 U7.10 U7.11
copper on no net:
  other v4: 23.44,24.432 23.44,30.432

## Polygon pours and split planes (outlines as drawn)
GND on Bottom Layer "GND_L02_P000" (solid, remove dead copper, pour order 0): 0,2.032 0,35.052 cw(c1.778,35.052) 1.778,36.83 30.48,36.83 cw(c30.48,35.052) 32.258,35.052 32.258,2.032 cw(c30.226,2.032) 30.226,0 2.032,0 cw(c2.032,2.032)
GND on Top Layer "GND_L01_P001" (solid, remove dead copper, pour order 1): 0,2.032 0,35.052 cw(c1.778,35.052) 1.778,36.83 30.48,36.83 cw(c30.48,35.052) 32.258,35.052 32.258,2.032 cw(c30.226,2.032) 30.226,0 2.032,0 cw(c2.032,2.032)

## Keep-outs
Keep-Out Layer:
  the board outline again, w0.254

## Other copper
Top Layer:
  rectangle net BAT_IN: 4.572,12.827 5.08,13.843
  rectangle net 3V3: 7.874,20.066 8.509,20.574
Bottom Layer:
  rectangle net BAT_IN: 4.445,12.827 5.207,16.256
  rectangle net USB_VCC: 22.86,8.89 23.368,10.033
  rectangle net 3V3: 17.526,11.43 18.034,11.938

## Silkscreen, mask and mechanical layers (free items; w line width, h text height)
Top Overlay:
  text "GND" at 9.257,32.258 h1.3 r90
  text "CLK" at 9.257,29.718 h1.3 r90
  text "DIO" at 9.257,27.178 h1.3 r90
  text "3.3" at 9.257,24.765 h1.3 r90
Bottom Overlay:
  text "GND" at 9.13,34.544 h1.3 r90
  text "CLK" at 9.13,31.877 h1.3 r90
  text "DIO" at 9.13,29.21 h1.3 r90
  text "3.3" at 9.13,26.416 h1.3 r90
Mechanical 1:
  the board outline again, w0.254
